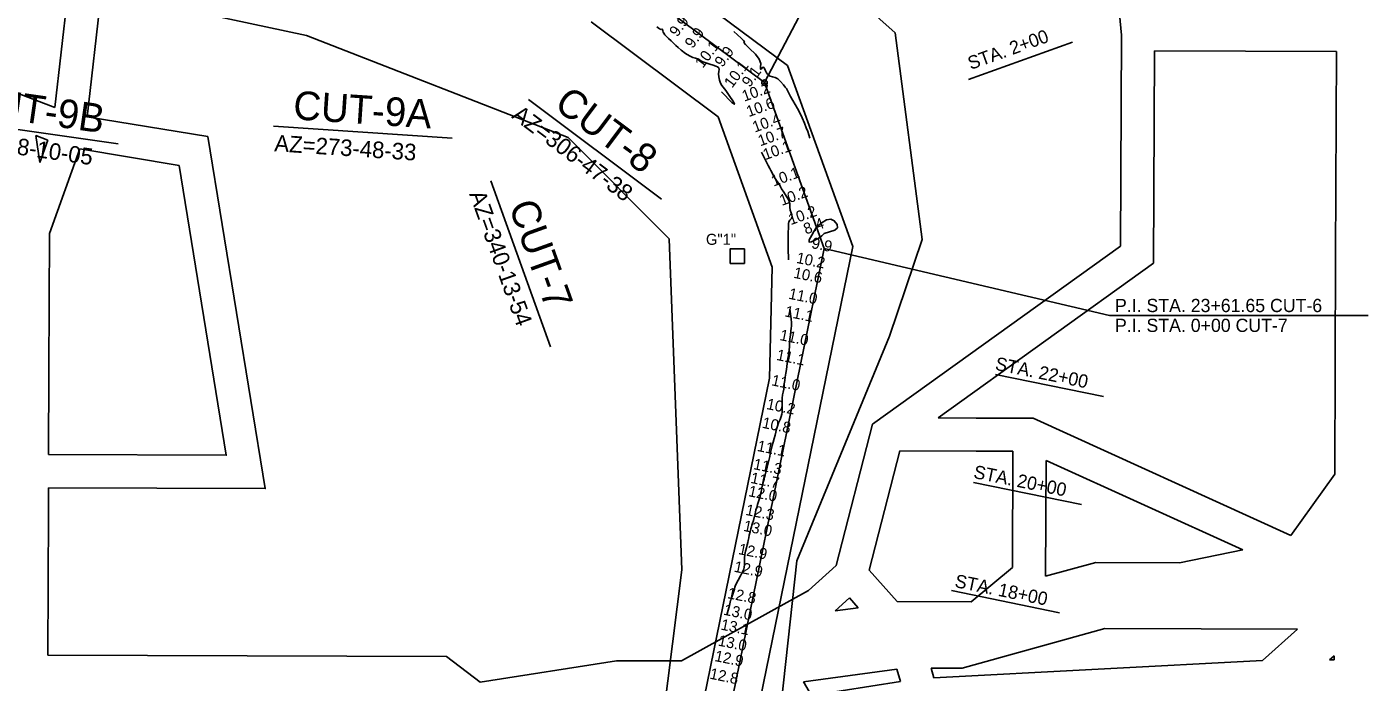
# Model space of a CAD drawing. Extents: x 501128 to 509328, y 1314906 to 1320706.
# Drawn here: x 504945 to 507376, y 1317196 to 1318384 of the extents above; entities that cross this region are included whole.
import ezdxf

# ---------------------------------------------------------------- set-up
doc = ezdxf.new("R2010")
doc.units = 0
for name, color, linetype in [('Level 1', 7, 'Continuous'), ('Level 14', 7, 'Continuous'), ('Level 23', 7, 'Continuous'), ('Level 32', 7, 'Continuous'), ('Level 49', 7, 'Continuous'), ('Level 5', 7, 'Continuous'), ('Level 50', 7, 'Continuous'), ('Level 51', 7, 'Continuous'), ('Level 52', 7, 'Continuous'), ('Level 56', 7, 'Continuous'), ('Level 6', 7, 'Continuous')]:
    doc.layers.add(name, color=color, linetype=linetype)

msp = doc.modelspace()

# ---------------------------------------------------------------- linework, layer by layer
at = {"layer": 'Level 1'}
for points in [[(506087.1, 1318384.3), (506091.7, 1318380.8), (506094.8, 1318379.3), (506096.3, 1318379.7), (506097.3, 1318379.4), (506097.8, 1318378.5), (506097.7, 1318376.8), (506098.3, 1318374.8), (506099.7, 1318372.5), (506101.7, 1318369.8), (506104.6, 1318366.6), (506108.3, 1318362.9), (506112.9, 1318358.8)], [(506112.9, 1318358.8), (506116.7, 1318355.2), (506119.6, 1318352.3), (506121.6, 1318350.1), (506125.5, 1318346.6), (506131.3, 1318341.8), (506139.1, 1318335.8), (506146, 1318331.5), (506152.1, 1318328.8), (506157.3, 1318327.7), (506161.5, 1318326.3), (506164.7, 1318324.6), (506166.8, 1318322.7), (506170.6, 1318320.7), (506176, 1318318.7), (506183.1, 1318316.6), (506188.9, 1318314.8), (506193.7, 1318313.2), (506197.2, 1318311.8), (506199.3, 1318309.7), (506200, 1318306.9), (506199.2, 1318303.4), (506199, 1318298.9), (506199.5, 1318293.6), (506200.6, 1318287.3), (506202.3, 1318282.1), (506204.5, 1318277.8), (506207.4, 1318274.6), (506211.9, 1318268.5), (506218, 1318259.7), (506225.7, 1318248.1), (506227.6, 1318243.7), (506223.6, 1318246.5), (506203.9, 1318266.5)], [(506226.6, 1318375.7), (506240, 1318363.8), (506244.1, 1318359.5), (506245.8, 1318356.9), (506244.9, 1318356), (506247.9, 1318352), (506254.8, 1318344.8), (506265.6, 1318334.6), (506272.5, 1318325.5), (506275.5, 1318317.7), (506274.6, 1318311.1), (506274.8, 1318307.6), (506276, 1318307.4), (506278.3, 1318310.5), (506280.4, 1318311), (506282.2, 1318308.9), (506283.8, 1318304.3), (506285.5, 1318300.7), (506287.4, 1318298.1), (506289.4, 1318296.4), (506292.4, 1318294.9), (506296.4, 1318293.6), (506301.3, 1318292.5), (506306.3, 1318289.7), (506311.3, 1318285.3), (506316.3, 1318279.3), (506319.7, 1318275.1), (506321.5, 1318272.9), (506321.7, 1318272.6), (506323, 1318269.9), (506325.6, 1318265), (506329.3, 1318257.7), (506333.3, 1318250.5), (506337.5, 1318243.4), (506342.1, 1318236.3), (506346.4, 1318228.4), (506350.5, 1318219.5), (506354.4, 1318209.7), (506357.7, 1318201.3), (506360.4, 1318194.2), (506364.5, 1318182.6)], [(506276.7, 1318157.1), (506285.4, 1318139.8), (506288.9, 1318132.7), (506291.7, 1318127.3), (506293.8, 1318123.5), (506295.8, 1318119.5), (506298, 1318115.3), (506300.2, 1318111), (506302.5, 1318107.1), (506304.9, 1318103.6), (506307.4, 1318100.5), (506309.3, 1318097.9), (506310.5, 1318095.7), (506311, 1318094), (506313.2, 1318090.2), (506317, 1318084.5), (506322.3, 1318076.8), (506326, 1318069.7), (506327.9, 1318063.1), (506328.1, 1318057.1), (506328.9, 1318051.8), (506330.2, 1318047.2), (506331.9, 1318043.3), (506332.2, 1318039.7), (506331, 1318036.5), (506328.2, 1318033.6), (506326.4, 1318030.6), (506325.4, 1318027.5), (506325.4, 1318024.3), (506325.4, 1318019.1), (506325.3, 1318012), (506325.3, 1318003), (506325.3, 1317993.3), (506325.3, 1317983.1), (506325.5, 1317961.6)], [(506328.1, 1317872.1), (506330.6, 1317854.5), (506331.2, 1317847.3), (506331.2, 1317841.7), (506330.5, 1317837.6), (506329.8, 1317832.2), (506329, 1317825.6), (506328.3, 1317817.6), (506327.7, 1317810.5), (506327.2, 1317804.1), (506326.8, 1317798.5), (506326.2, 1317793.2), (506325.4, 1317788.1), (506324.4, 1317783.2), (506323.6, 1317778.3), (506323, 1317773.4), (506322.6, 1317768.5), (506321.9, 1317762.8), (506321, 1317756.3), (506319.8, 1317749.1), (506318.8, 1317742.7), (506318, 1317737), (506317.5, 1317732), (506316.9, 1317727), (506316, 1317721.9), (506314.9, 1317716.6), (506314.2, 1317710.6), (506314, 1317703.9), (506314.2, 1317696.4), (506314.3, 1317690.2), (506314.1, 1317685.3), (506313.8, 1317681.8), (506312.6, 1317677.4), (506310.6, 1317672.1), (506307.8, 1317665.9), (506305.6, 1317660.1), (506303.9, 1317654.5), (506302.7, 1317649.3), (506301.3, 1317643.6), (506299.6, 1317637.5), (506297.7, 1317631), (506296.1, 1317625), (506294.7, 1317619.5), (506293.7, 1317614.7), (506292.6, 1317609.9), (506291.5, 1317605.1), (506290.4, 1317600.3), (506289.2, 1317595.6), (506288, 1317590.8), (506286.7, 1317586), (506285.5, 1317581.2), (506284.4, 1317576.6), (506283.4, 1317572), (506282.4, 1317567.8), (506281.3, 1317564), (506280.1, 1317560.5), (506278.9, 1317556.3), (506277.8, 1317551.2), (506276.8, 1317545.3), (506275.8, 1317540.3), (506274.9, 1317536.1), (506274, 1317532.8), (506272.8, 1317528.7), (506271.3, 1317523.7), (506269.5, 1317518)], [(506269.5, 1317518), (506268, 1317512.8), (506266.7, 1317508.1), (506265.8, 1317503.9), (506264.7, 1317499.3), (506263.4, 1317494.3), (506261.9, 1317488.8), (506260.6, 1317484.2), (506259.4, 1317480.5), (506258.4, 1317477.6), (506257.2, 1317473.6), (506256, 1317468.7), (506254.6, 1317462.6), (506253.5, 1317457.4), (506252.5, 1317453), (506251.8, 1317449.3), (506250.7, 1317444.8), (506249.2, 1317439.6), (506247.4, 1317433.6), (506246.2, 1317427.4), (506245.7, 1317420.9), (506246, 1317414.2), (506245.9, 1317408.6), (506245.4, 1317404.1), (506244.5, 1317400.7), (506242.4, 1317395.7), (506238.9, 1317388.9), (506234.2, 1317380.5), (506230.8, 1317374.2), (506229, 1317370.2), (506228.5, 1317368.3), (506227.5, 1317364.7), (506225.8, 1317359.2), (506223.4, 1317352), (506221.8, 1317347), (506220.9, 1317344.3), (506220.8, 1317343.8), (506219.9, 1317340.7), (506218.4, 1317334.9), (506214.1, 1317318.1)]]:
    msp.add_lwpolyline(points, dxfattribs=at)
msp.add_lwpolyline([(506390.1, 1318009.6), (506386.3, 1318005.2), (506382.2, 1318002.2), (506375.8, 1317998.6), (506367.2, 1317994.2), (506363, 1317994), (506363.2, 1317998.1), (506367.8, 1318006.3), (506371.5, 1318012.9), (506374.4, 1318017.8), (506376.4, 1318020.9), (506380.5, 1318024.7), (506386.6, 1318029.2), (506394.8, 1318034.3), (506402.2, 1318035.4), (506408.6, 1318032.5), (506414.1, 1318025.6), (506414.5, 1318020), (506409.8, 1318015.6)], close=True, dxfattribs=at)
at = {"layer": 'Level 14'}
for p, q in [((507317.2, 1317969.5), (507318.6, 1318339.4)), ((507315.7, 1317573.3), (507317.2, 1317969.5)), ((506791.6, 1317387.9), (506882.6, 1317413.1)), ((507034.3, 1317412.5), (506882.6, 1317413.1)), ((506361.6, 1317362.3), (506131.9, 1317234.2)), ((506656.9, 1317341.3), (506522.3, 1317341.8)), ((506452, 1317330.9), (506410, 1317325.1)), ((506898.7, 1317293), (506640.2, 1317221.3)), ((507248.3, 1317291.7), (506898.7, 1317293)), ((507314.5, 1317236.1), (507314.5, 1317243.6)), ((506013.7, 1317234.6), (505766.9, 1317195.9)), ((506131.9, 1317234.2), (506013.7, 1317234.6)), ((506522.2, 1317219.4), (506352.7, 1317196.2)), ((506640.2, 1317221.3), (506584.1, 1317221.5))]:
    msp.add_line(p, q, dxfattribs=at)
at = {"layer": 'Level 23'}
for p, q in [((507184.9, 1317235), (507248.3, 1317291.7)), ((507306.1, 1317236.1), (507314.5, 1317243.6)), ((506352.7, 1317196.2), (506367.2, 1317171.5))]:
    msp.add_line(p, q, dxfattribs=at)
at = {"layer": 'Level 32'}
for p, q in [((506929.1, 1318369.4), (506900.5, 1318670.6)), ((504996, 1318238.1), (505025.3, 1318493.1)), ((505054.5, 1318221.3), (505084.3, 1318481)), ((506927.6, 1317986.3), (506929.1, 1318369.4)), ((506987.5, 1317955.4), (506988.9, 1318340.7)), ((507318.6, 1318339.4), (506988.9, 1318340.7)), ((504996, 1318238.1), (504931.1, 1318262.7)), ((505273.4, 1318185.2), (505054.5, 1318221.3)), ((504983.2, 1318178.8), (504961.7, 1318187)), ((504968.7, 1318138.3), (504961.7, 1318187)), ((504968.7, 1318138.3), (504983.2, 1318178.8)), ((504986.2, 1318009.5), (505041.2, 1318162.7)), ((505221.1, 1318133), (505041.2, 1318162.7)), ((504985.2, 1317760.2), (504986.2, 1318009.5)), ((506478, 1317663.4), (506927.6, 1317986.3)), ((506597.1, 1317675), (506987.5, 1317955.4)), ((504984.6, 1317608.5), (504985.2, 1317760.2)), ((506665.9, 1317674.8), (506597.1, 1317675)), ((506769.2, 1317674.4), (506665.9, 1317674.8)), ((507236, 1317462), (506769.2, 1317674.4)), ((506412, 1317407.4), (506478, 1317663.4)), ((506471.8, 1317399.1), (506527.6, 1317615.3)), ((506665.7, 1317614.8), (506527.6, 1317615.3)), ((506732.5, 1317614.5), (506665.7, 1317614.8)), ((506792.4, 1317597.9), (506791.6, 1317387.9)), ((507149.1, 1317435.6), (506792.4, 1317597.9)), ((507236, 1317462), (507315.7, 1317573.3)), ((504984.2, 1317505.7), (504984.4, 1317548.5)), ((504983.2, 1317244.9), (504984.2, 1317505.7)), ((507149.1, 1317435.6), (507034.3, 1317412.5)), ((506361.6, 1317362.3), (506412, 1317407.4)), ((506522.3, 1317341.8), (506471.8, 1317399.1)), ((506410, 1317325.1), (506436.3, 1317348.6)), ((506452, 1317330.9), (506436.3, 1317348.6)), ((507306.1, 1317236.1), (507314.5, 1317236.1)), ((506522.2, 1317219.4), (506528.8, 1317196.9)), ((506584.1, 1317221.5), (506589.3, 1317203.7)), ((506589.3, 1317203.7), (507184.9, 1317235)), ((506367.2, 1317171.5), (506528.8, 1317196.9))]:
    msp.add_line(p, q, dxfattribs=at)
for points in [[(504984.4, 1317548.5), (505377.2, 1317547), (505273.4, 1318185.2)], [(504984.6, 1317608.5), (505306.6, 1317607.2), (505221.1, 1318133)], [(506732.5, 1317614.5), (506731.7, 1317404), (506656.9, 1317341.3)], [(505766.9, 1317195.9), (505705.7, 1317242.2), (504983.2, 1317244.9)]]:
    msp.add_lwpolyline(points, dxfattribs=at)
at = {"layer": 'Level 5'}
for points in [[(502988.5, 1320506.3), (503056.9, 1320142.4), (503189.4, 1319858.7), (503438.4, 1319516.2), (504086.3, 1318789.2), (504252.7, 1318680.4), (504544, 1318562.8), (505451.9, 1318368.4), (505926.4, 1318183.7), (506109.2, 1317999.8), (506132.4, 1317399.6), (506064.1, 1316858.1), (505929.2, 1316350.1), (505744.2, 1315800.6), (505760.3, 1315617.2), (505843.1, 1315416.9), (505867.7, 1315106.3)], [(506133.9, 1315106.3), (506134.1, 1315191), (506100.8, 1315216.1), (506088.6, 1315786), (506137, 1316149.5), (506179.5, 1316449.4), (506272.3, 1316790.8), (506340.8, 1317415.6), (506508.7, 1317823.5), (506567.6, 1317998.4), (506518.7, 1318373.6), (506369, 1318507.4), (506052.8, 1318658.3), (505377.9, 1318693.7), (504936.3, 1318761.6), (504770.1, 1318912.2), (504728.7, 1319020.6), (504387.5, 1319163.3), (503822.6, 1319798.4), (503531.7, 1320041), (503232.9, 1320458.6), (503215.7, 1320506.3)]]:
    msp.add_lwpolyline(points, dxfattribs=at)
at = {"layer": 'Level 50'}
for p, q in [((506324, 1318314.1), (506022, 1318540)), ((506198.1, 1318220.9), (505967.7, 1318393.3)), ((506442, 1317985.8), (506324, 1318314.1)), ((506296.1, 1317948.2), (506198.1, 1318220.9)), ((505969.1, 1315668), (506442, 1317985.8)), ((506291.3, 1317747.1), (506296.1, 1317948.2)), ((505867, 1315668.2), (506291.3, 1317747.1))]:
    msp.add_line(p, q, dxfattribs=at)
at = {"layer": 'Level 51'}
for p, q in [((506095.7, 1318071.9), (505854.3, 1318252.5)), ((505110.8, 1318171.8), (504813.4, 1318214.5)), ((505716.2, 1318182.3), (505391.9, 1318203.9)), ((505894.1, 1317803.8), (505786, 1318104.7))]:
    msp.add_line(p, q, dxfattribs=at)
msp.add_circle((506282.1, 1318283), 5, dxfattribs=at)
at = {"layer": 'Level 52'}
msp.add_lwpolyline([(506219.6, 1317955.2), (506219.6, 1317981.4), (506245.8, 1317981.4), (506245.8, 1317955.2)], close=True, dxfattribs=at)
at = {"layer": 'Level 56'}
for p, q in [((506282.1, 1318283), (506445.8, 1318596.4)), ((506652, 1318288.6), (506840.2, 1318356.3)), ((506390.2, 1317982.1), (506907.4, 1317860.9)), ((506907.4, 1317860.9), (507376.3, 1317860.9)), ((506896.8, 1317713.7), (506700.8, 1317753.7)), ((506856.8, 1317517.8), (506660.9, 1317557.7)), ((506816.8, 1317321.8), (506620.9, 1317361.8))]:
    msp.add_line(p, q, dxfattribs=at)
at = {"layer": 'Level 6'}
for p, q in [((506282.1, 1318283), (506040.6, 1318463.6)), ((506390.2, 1317982.1), (506282.1, 1318283)), ((505918.1, 1315668.1), (506390.2, 1317982.1))]:
    msp.add_line(p, q, dxfattribs=at)

# ---------------------------------------------------------------- texts
at = {"layer": 'Level 49'}
for s, rotation, p in [('9.9', 53.2061, (506123.8, 1318364.7)), ('9.9', 53.2061, (506151.8, 1318343.7)), ('10.1 ', 53.2061, (506170.3, 1318308)), ('9.9', 53.2061, (506205.8, 1318309.7)), ('10.1 ', 53.2061, (506223.3, 1318272)), ('9.1', 53.2061, (506255.2, 1318273.3)), ('10.2 ', 19.7683, (506245.5, 1318248.4)), ('10.6 ', 19.7683, (506253.5, 1318220.4)), ('10.4 ', 19.7683, (506264.5, 1318192.4)), ('10.7 ', 19.7683, (506274.5, 1318167.4)), ('10.1 ', 19.7683, (506283.5, 1318142.4)), ('10.1 ', 19.7683, (506298.5, 1318094.4)), ('10.2 ', 19.7683, (506313.5, 1318059.4)), ('10.2 ', 19.7683, (506329.5, 1318024.4)), ('8.4', 19.7683, (506357.1, 1318007.5)), ('9.9', 348.4669, (506366.1, 1317983.2)), ('10.2 ', 348.4669, (506338.7, 1317956.3)), ('10.6 ', 348.4669, (506333.7, 1317929.3)), ('11.0 ', 348.4669, (506324.7, 1317891.3)), ('11.1 ', 348.4669, (506317.7, 1317859.3)), ('11.0 ', 348.4669, (506308.7, 1317816.3)), ('11.1 ', 348.4669, (506302.7, 1317780.3)), ('11.0 ', 348.4669, (506293.7, 1317734.3)), ('10.2 ', 348.4669, (506284.7, 1317691.3)), ('10.8 ', 348.4669, (506276.7, 1317657.3)), ('11.1 ', 348.4669, (506267.7, 1317615.3)), ('11.3 ', 348.4669, (506260.7, 1317582.3)), ('11.7 ', 348.4669, (506255.7, 1317557.3)), ('12.0 ', 348.4669, (506251.7, 1317533.3)), ('12.3 ', 348.4669, (506246.7, 1317499.3)), ('13.0 ', 348.4669, (506242.7, 1317470.3)), ('12.9 ', 348.4669, (506233.7, 1317428.3)), ('12.9 ', 348.4669, (506225.7, 1317396.3)), ('12.8 ', 348.4669, (506213.7, 1317348.3)), ('13.0 ', 348.4669, (506206.7, 1317318.3)), ('13.1 ', 348.4669, (506201.7, 1317291.3)), ('13.0 ', 348.4669, (506196.7, 1317262.3)), ('12.9 ', 348.4669, (506190.7, 1317234.3)), ('12.8 ', 348.4669, (506181.7, 1317202.3))]:
    msp.add_text(s, height=20, rotation=rotation, dxfattribs=at).set_placement(p)
at = {"layer": 'Level 51'}
for s, height, rotation, p in [('CUT-9B', 52, 351.832, (504833.4, 1318226.8)), ('CUT-9A', 52, 356.1907, (505426.8, 1318216.6)), ('CUT-8', 52, 323.2061, (505898.4, 1318238.2)), ('AZ=306-47-38', 30, 323.2061, (505822.5, 1318220.1)), ('AZ=278-10-05', 30, 351.832, (504807.6, 1318169.9)), ('AZ=273-48-33', 30, 356.1907, (505393.1, 1318158.7)), ('AZ=340-13-54', 30, 289.7682, (505746.6, 1318081.2)), ('CUT-7', 52, 289.7682, (505818.1, 1318059.7))]:
    msp.add_text(s, height=height, rotation=rotation, dxfattribs=at).set_placement(p)
at = {"layer": 'Level 52'}
msp.add_text('G"1"', height=20, dxfattribs=at).set_placement((506176, 1317988.9))
at = {"layer": 'Level 56'}
for s, rotation, p in [('STA. 2+00', 19.7682, (506655.9, 1318306)), ('STA. 22+00', 348.542, (506698.9, 1317762.4)), ('STA. 20+00', 348.542, (506659.7, 1317566.2)), ('STA. 18+00', 348.542, (506625.6, 1317368.4))]:
    msp.add_text(s, height=24, rotation=rotation, dxfattribs=at).set_placement(p)
for s, p in [('P.I. STA. 23+61.65 CUT-6', (506917.4, 1317866.9)), ('P.I. STA. 0+00 CUT-7', (506917.4, 1317830.9))]:
    msp.add_text(s, height=24, dxfattribs=at).set_placement(p)

doc.saveas('drawing.dxf')
